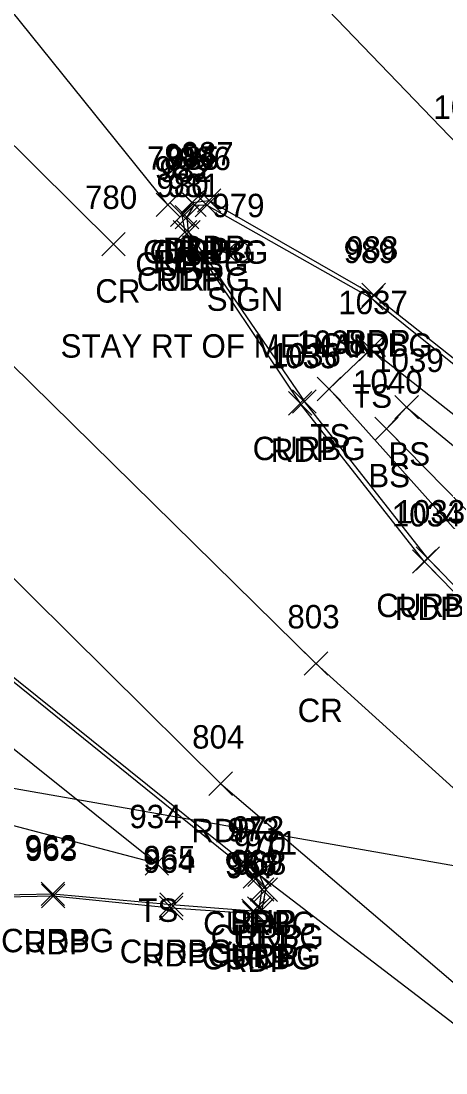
# Model space of a CAD drawing. Extents: x 1688195 to 1692013, y 424605 to 441234.
# Drawn here: x 1691786.9 to 1691823.2, y 439243.2 to 439333.1 of the extents above; entities that cross this region are included whole.
import ezdxf

# ---------------------------------------------------------------- set-up
doc = ezdxf.new("R2010")
doc.units = 0
for name, color, linetype in [('DCP', 7, 'Continuous'), ('L_A', 7, 'Continuous'), ('L_I', 7, 'Continuous'), ('L_TIC', 7, 'Continuous'), ('LELB', 7, 'Continuous'), ('P_A', 7, 'Continuous'), ('P_I', 7, 'Continuous'), ('P_TIC', 7, 'Continuous'), ('PET', 7, 'Continuous'), ('PRC', 7, 'Continuous'), ('PSP', 7, 'Continuous'), ('R_A', 7, 'Continuous'), ('R_I', 7, 'Continuous'), ('R_TIC', 7, 'Continuous'), ('RC', 7, 'Continuous'), ('S_A', 7, 'Continuous'), ('S_C', 7, 'Continuous'), ('S_I', 7, 'Continuous'), ('SSGN', 7, 'Continuous')]:
    doc.layers.add(name, color=color, linetype=linetype)

msp = doc.modelspace()

# ---------------------------------------------------------------- linework, layer by layer
at = {"layer": 'DCP'}
msp.add_lwpolyline([(1691774.059, 439269.686), (1691869.305, 439252.966)], dxfattribs=at)
at = {"layer": 'L_TIC'}
for points in [[(1691815.816, 439304.046), (1691817.816, 439306.046)], [(1691817.816, 439304.046), (1691815.816, 439306.046)], [(1691815.816, 439304.046), (1691817.816, 439306.046)], [(1691817.816, 439304.046), (1691815.816, 439306.046)], [(1691812.249, 439300.655), (1691814.249, 439302.655)], [(1691814.249, 439300.655), (1691812.249, 439302.655)], [(1691818.881, 439299.105), (1691820.881, 439301.105)], [(1691820.881, 439299.105), (1691818.881, 439301.105)], [(1691818.881, 439299.105), (1691820.881, 439301.105)], [(1691820.881, 439299.105), (1691818.881, 439301.105)], [(1691817.164, 439297.257), (1691819.164, 439299.257)], [(1691819.164, 439297.257), (1691817.164, 439299.257)], [(1691797.546, 439260.132), (1691799.546, 439262.132)], [(1691799.546, 439260.132), (1691797.546, 439262.132)]]:
    msp.add_lwpolyline(points, dxfattribs=at)
at = {"layer": 'LELB'}
for points in [[(1691816.816, 439305.046), (1691813.249, 439301.655), (1691833.998, 439278.476), (1691859.792, 439254.715), (1691864.22, 439256.101), (1691869.31, 439257.053)], [(1691816.816, 439305.046), (1691841.88, 439285.31), (1691864.803, 439264.192), (1691872.176, 439257.99), (1691876.774, 439253.036), (1691872.187, 439248.373), (1691865.531, 439250.784)], [(1691819.881, 439300.105), (1691818.164, 439298.257), (1691836.42, 439279.689), (1691861.134, 439258.993), (1691864.22, 439256.101)], [(1691819.881, 439300.105), (1691839.882, 439283.636), (1691863.807, 439262.535), (1691869.31, 439257.053)], [(1691771.366, 439276.277), (1691768.238, 439279.008), (1691771.864, 439282.457), (1691798.546, 439261.132), (1691782.923, 439265.227), (1691769.459, 439260.809), (1691759.054, 439260.351), (1691756.036, 439264.348), (1691762.781, 439272.129), (1691769.275, 439265.641)]]:
    msp.add_lwpolyline(points, dxfattribs=at)
at = {"layer": 'P_TIC'}
for points in [[(1691798.482, 439316.379), (1691800.482, 439318.379)], [(1691800.482, 439316.379), (1691798.482, 439318.379)], [(1691800.542, 439316.586), (1691802.542, 439318.586)], [(1691802.542, 439316.586), (1691800.542, 439318.586)], [(1691802.007, 439316.751), (1691804.007, 439318.751)], [(1691804.007, 439316.751), (1691802.007, 439318.751)], [(1691799.709, 439315.533), (1691801.709, 439317.533)], [(1691801.709, 439315.533), (1691799.709, 439317.533)], [(1691799.945, 439314.05), (1691801.945, 439316.05)], [(1691801.945, 439314.05), (1691799.945, 439316.05)], [(1691799.945, 439314.05), (1691801.945, 439316.05)], [(1691801.945, 439314.05), (1691799.945, 439316.05)], [(1691793.844, 439313.033), (1691795.844, 439315.033)], [(1691795.844, 439313.033), (1691793.844, 439315.033)], [(1691816.064, 439308.697), (1691818.064, 439310.697)], [(1691818.064, 439308.697), (1691816.064, 439310.697)], [(1691809.775, 439299.426), (1691811.775, 439301.426)], [(1691811.775, 439299.426), (1691809.775, 439301.426)], [(1691809.775, 439299.426), (1691811.775, 439301.426)], [(1691811.775, 439299.426), (1691809.775, 439301.426)], [(1691820.385, 439285.908), (1691822.385, 439287.908)], [(1691822.385, 439285.908), (1691820.385, 439287.908)], [(1691811.134, 439277.202), (1691813.134, 439279.202)], [(1691813.134, 439277.202), (1691811.134, 439279.202)], [(1691802.993, 439266.935), (1691804.993, 439268.935)], [(1691804.993, 439266.935), (1691802.993, 439268.935)], [(1691806.317, 439259.152), (1691808.317, 439261.152)], [(1691808.317, 439259.152), (1691806.317, 439261.152)], [(1691806.317, 439259.152), (1691808.317, 439261.152)], [(1691808.317, 439259.152), (1691806.317, 439261.152)], [(1691806.85, 439257.884), (1691808.85, 439259.884)], [(1691808.85, 439257.884), (1691806.85, 439259.884)], [(1691788.686, 439257.345), (1691790.686, 439259.345)], [(1691790.686, 439257.345), (1691788.686, 439259.345)], [(1691798.766, 439256.32), (1691800.766, 439258.32)], [(1691800.766, 439256.32), (1691798.766, 439258.32)], [(1691805.846, 439255.861), (1691807.846, 439257.861)], [(1691807.846, 439255.861), (1691805.846, 439257.861)], [(1691806.547, 439256.165), (1691808.547, 439258.165)], [(1691808.547, 439256.165), (1691806.547, 439258.165)]]:
    msp.add_lwpolyline(points, dxfattribs=at)
at = {"layer": 'PET'}
for points in [[(1691703.519, 439378.215), (1691727.927, 439348.964), (1691752.514, 439320.765), (1691774.827, 439296.788), (1691803.993, 439267.935), (1691829.698, 439246.009), (1691860.192, 439220.256)], [(1691800.945, 439315.05), (1691800.709, 439316.533), (1691801.542, 439317.586), (1691803.007, 439317.751), (1691817.064, 439309.697), (1691828.512, 439300.647), (1691844.684, 439285.422), (1691865.174, 439267.394), (1691884.848, 439250.831), (1691897.532, 439239.425), (1691910.299, 439227.429), (1691911.518, 439225.273), (1691910.888, 439223.79), (1691909.812, 439223.418), (1691908.764, 439223.597), (1691890.09, 439233.403), (1691870.381, 439245.165), (1691862.377, 439250.392), (1691860.033, 439251.797), (1691851.002, 439258.938), (1691829.097, 439279.042), (1691821.385, 439286.908), (1691810.775, 439300.426)], [(1691800.945, 439315.05), (1691810.775, 439300.426)], [(1691773.94, 439286.942), (1691772.103, 439287.435), (1691770.661, 439286.747), (1691766.651, 439282.324), (1691764.751, 439279.868), (1691762.264, 439277.277), (1691760.226, 439275.573), (1691740.661, 439255.171), (1691740.072, 439254), (1691740.179, 439252.79), (1691740.939, 439251.644), (1691743.3, 439251.04), (1691755.388, 439254.219), (1691767.334, 439256.47), (1691772.069, 439257.236), (1691781.375, 439258.188), (1691789.686, 439258.345), (1691799.766, 439257.32), (1691806.846, 439256.861), (1691807.547, 439257.165), (1691807.85, 439258.884), (1691807.317, 439260.152)]]:
    msp.add_lwpolyline(points, dxfattribs=at)
at = {"layer": 'PRC'}
for points in [[(1691980.661, 439193.959), (1691949.028, 439215.605), (1691915.391, 439241.551), (1691887.198, 439265.051), (1691850.384, 439298.072), (1691824.991, 439321.732), (1691796.941, 439350.893), (1691771.504, 439379.218), (1691742.052, 439414.412)], [(1691721.974, 439394.364), (1691745.645, 439365.634), (1691767.872, 439340.76), (1691794.844, 439314.033)], [(1691713.182, 439386.477), (1691737.313, 439357.714), (1691761.172, 439330.745), (1691784.31, 439305.517), (1691812.134, 439278.202), (1691838.297, 439254.51), (1691867.441, 439230.247), (1691889.259, 439214.415), (1691920.444, 439189.798), (1691954.552, 439163.68)], [(1691799.482, 439317.379), (1691771.685, 439351.898), (1691744.242, 439385.863)]]:
    msp.add_lwpolyline(points, dxfattribs=at)
at = {"layer": 'PSP'}
msp.add_lwpolyline([(1691696.132, 439372.686), (1691709.548, 439355.191), (1691723.603, 439339.325), (1691742.747, 439319), (1691750.974, 439309.526), (1691763.384, 439297.713), (1691773.94, 439286.942), (1691807.317, 439260.152), (1691827.219, 439244.924), (1691853.912, 439221.372)], dxfattribs=at)
at = {"layer": 'R_TIC'}
for points in [[(1691800.764, 439316.377), (1691802.764, 439318.377)], [(1691802.764, 439316.377), (1691800.764, 439318.377)], [(1691801.82, 439316.349), (1691803.82, 439318.349)], [(1691803.82, 439316.349), (1691801.82, 439318.349)], [(1691800.115, 439315.331), (1691802.115, 439317.331)], [(1691802.115, 439315.331), (1691800.115, 439317.331)], [(1691800.246, 439314.044), (1691802.246, 439316.044)], [(1691802.246, 439314.044), (1691800.246, 439316.044)], [(1691800.246, 439314.044), (1691802.246, 439316.044)], [(1691802.246, 439314.044), (1691800.246, 439316.044)], [(1691815.869, 439308.413), (1691817.869, 439310.413)], [(1691817.869, 439308.413), (1691815.869, 439310.413)], [(1691810.14, 439299.575), (1691812.14, 439301.575)], [(1691812.14, 439299.575), (1691810.14, 439301.575)], [(1691810.14, 439299.575), (1691812.14, 439301.575)], [(1691812.14, 439299.575), (1691810.14, 439301.575)], [(1691820.702, 439286.165), (1691822.702, 439288.165)], [(1691822.702, 439286.165), (1691820.702, 439288.165)], [(1691805.912, 439259.006), (1691807.912, 439261.006)], [(1691807.912, 439259.006), (1691805.912, 439261.006)], [(1691805.912, 439259.006), (1691807.912, 439261.006)], [(1691807.912, 439259.006), (1691805.912, 439261.006)], [(1691788.646, 439257.537), (1691790.646, 439259.537)], [(1691790.646, 439257.537), (1691788.646, 439259.537)], [(1691806.547, 439257.894), (1691808.547, 439259.894)], [(1691808.547, 439257.894), (1691806.547, 439259.894)], [(1691798.787, 439256.621), (1691800.787, 439258.621)], [(1691800.787, 439256.621), (1691798.787, 439258.621)], [(1691805.795, 439256.068), (1691807.795, 439258.068)], [(1691807.795, 439256.068), (1691805.795, 439258.068)], [(1691806.286, 439256.282), (1691808.286, 439258.282)], [(1691808.286, 439256.282), (1691806.286, 439258.282)]]:
    msp.add_lwpolyline(points, dxfattribs=at)
at = {"layer": 'RC'}
for points in [[(1691801.246, 439315.044), (1691801.115, 439316.331), (1691801.764, 439317.377), (1691802.82, 439317.349), (1691816.869, 439309.413), (1691828.254, 439300.3), (1691844.418, 439285.107), (1691865.016, 439267.121), (1691884.737, 439250.475), (1691897.458, 439238.929), (1691910.163, 439227.134), (1691911.269, 439225.368), (1691910.647, 439224.032), (1691909.839, 439223.784), (1691908.933, 439223.978), (1691890.407, 439233.729), (1691870.585, 439245.445), (1691863.213, 439250.357), (1691862.377, 439250.392)], [(1691801.246, 439315.044), (1691811.14, 439300.575)], [(1691860.033, 439251.797), (1691859.706, 439252.995), (1691851.486, 439259.157), (1691829.315, 439279.332), (1691821.702, 439287.165), (1691811.14, 439300.575)], [(1691773.768, 439286.756), (1691806.912, 439260.006)], [(1691762.264, 439277.277), (1691760.343, 439275.452), (1691741.032, 439255.066), (1691740.637, 439253.822), (1691740.67, 439252.826), (1691741.357, 439252.113), (1691743.083, 439251.766), (1691755.326, 439254.607), (1691767.334, 439256.888), (1691771.771, 439257.775), (1691781.171, 439258.359), (1691789.646, 439258.537), (1691799.787, 439257.621), (1691806.795, 439257.068), (1691807.286, 439257.282), (1691807.547, 439258.894), (1691806.912, 439260.006)]]:
    msp.add_lwpolyline(points, dxfattribs=at)
at = {"layer": 'SSGN'}
for p, q in [((1691804.016, 439314.184), (1691807.349, 439314.184)), ((1691805.663, 439313.35), (1691805.663, 439313.35))]:
    msp.add_line(p, q, dxfattribs=at)
msp.add_circle((1691805.663, 439313.35), 0.833, dxfattribs=at)

# ---------------------------------------------------------------- texts
at = {"layer": 'L_A'}
for s, p in [('TS', (1691815.225, 439300.046)), ('TS', (1691815.225, 439300.046)), ('TS', (1691811.658, 439296.655)), ('BS', (1691818.322, 439295.105)), ('BS', (1691818.322, 439295.105)), ('BS', (1691816.605, 439293.257)), ('TS', (1691796.956, 439256.132))]:
    msp.add_text(s, height=2, dxfattribs=at).set_placement(p)
at = {"layer": 'L_I'}
for s, p in [('1037', (1691814.044, 439308.046)), ('1037', (1691814.044, 439308.046)), ('1038', (1691810.477, 439304.655)), ('1039', (1691817.102, 439303.105)), ('1039', (1691817.102, 439303.105)), ('1040', (1691815.306, 439301.257)), ('934', (1691796.184, 439264.132))]:
    msp.add_text(s, height=2, dxfattribs=at).set_placement(p)
at = {"layer": 'P_A'}
for s, p in [('CR', (1691797.915, 439312.379)), ('RDP', (1691799.03, 439312.586)), ('RDP', (1691800.495, 439312.751)), ('RDP', (1691798.197, 439311.533)), ('RDP', (1691798.433, 439310.05)), ('RDP', (1691798.433, 439310.05)), ('CR', (1691793.277, 439309.033)), ('RDP', (1691814.553, 439304.697)), ('RDP', (1691808.264, 439295.426)), ('RDP', (1691808.264, 439295.426)), ('RDP', (1691818.873, 439281.908)), ('CR', (1691810.567, 439273.202)), ('RDP', (1691801.481, 439262.935)), ('SHP', (1691804.853, 439255.152)), ('RDP', (1691804.805, 439255.152)), ('RDP', (1691787.174, 439253.345)), ('RDP', (1691805.338, 439253.884)), ('RDP', (1691797.255, 439252.32)), ('RDP', (1691805.036, 439252.165)), ('RDP', (1691804.335, 439251.861))]:
    msp.add_text(s, height=2, dxfattribs=at).set_placement(p)
at = {"layer": 'P_I'}
for s, p in [('1067', (1691822.172, 439324.732)), ('984', (1691799.18, 439320.586)), ('987', (1691800.645, 439320.751)), ('781', (1691797.687, 439320.379)), ('983', (1691798.346, 439319.533)), ('980', (1691798.496, 439318.05)), ('980', (1691798.496, 439318.05)), ('780', (1691792.395, 439317.033)), ('988', (1691814.702, 439312.697)), ('1035', (1691808.004, 439303.426)), ('1035', (1691808.004, 439303.426)), ('1034', (1691818.614, 439289.908)), ('803', (1691809.693, 439281.202)), ('804', (1691801.552, 439270.935)), ('972', (1691804.955, 439263.152)), ('972', (1691804.955, 439263.152)), ('963', (1691787.277, 439261.345)), ('971', (1691806.055, 439261.884)), ('964', (1691797.357, 439260.32)), ('967', (1691804.437, 439259.861)), ('968', (1691805.138, 439260.165))]:
    msp.add_text(s, height=2, dxfattribs=at).set_placement(p)
at = {"layer": 'R_A'}
for p in [(1691797.347, 439312.377), (1691798.403, 439312.349), (1691796.697, 439311.331), (1691796.829, 439310.044), (1691796.829, 439310.044), (1691812.452, 439304.413), (1691806.722, 439295.575), (1691806.722, 439295.575), (1691817.284, 439282.165), (1691802.494, 439255.006), (1691802.494, 439255.006), (1691785.229, 439253.537), (1691803.129, 439253.894), (1691795.369, 439252.621), (1691802.869, 439252.282), (1691802.378, 439252.068)]:
    msp.add_text('CURBG', height=2, dxfattribs=at).set_placement(p)
at = {"layer": 'R_I'}
for s, p in [('985', (1691799.402, 439320.377)), ('986', (1691800.403, 439320.349)), ('982', (1691798.752, 439319.331)), ('981', (1691799.451, 439318.044)), ('981', (1691799.451, 439318.044)), ('989', (1691814.499, 439312.413)), ('1036', (1691808.313, 439303.575)), ('1036', (1691808.313, 439303.575)), ('1033', (1691818.93, 439290.165)), ('973', (1691804.549, 439263.006)), ('973', (1691804.549, 439263.006)), ('962', (1691787.236, 439261.537)), ('970', (1691805.098, 439261.894)), ('965', (1691797.377, 439260.621)), ('969', (1691804.869, 439260.282)), ('966', (1691804.33, 439260.068))]:
    msp.add_text(s, height=2, dxfattribs=at).set_placement(p)
at = {"layer": 'S_A'}
msp.add_text('SIGN', height=2, dxfattribs=at).set_placement((1691802.801, 439308.33))
at = {"layer": 'S_C'}
msp.add_text('STAY RT OF MEDIAN', height=2, dxfattribs=at).set_placement((1691790.313, 439304.33))
at = {"layer": 'S_I'}
msp.add_text('979', height=2, dxfattribs=at).set_placement((1691803.273, 439316.33))

doc.saveas('drawing.dxf')
